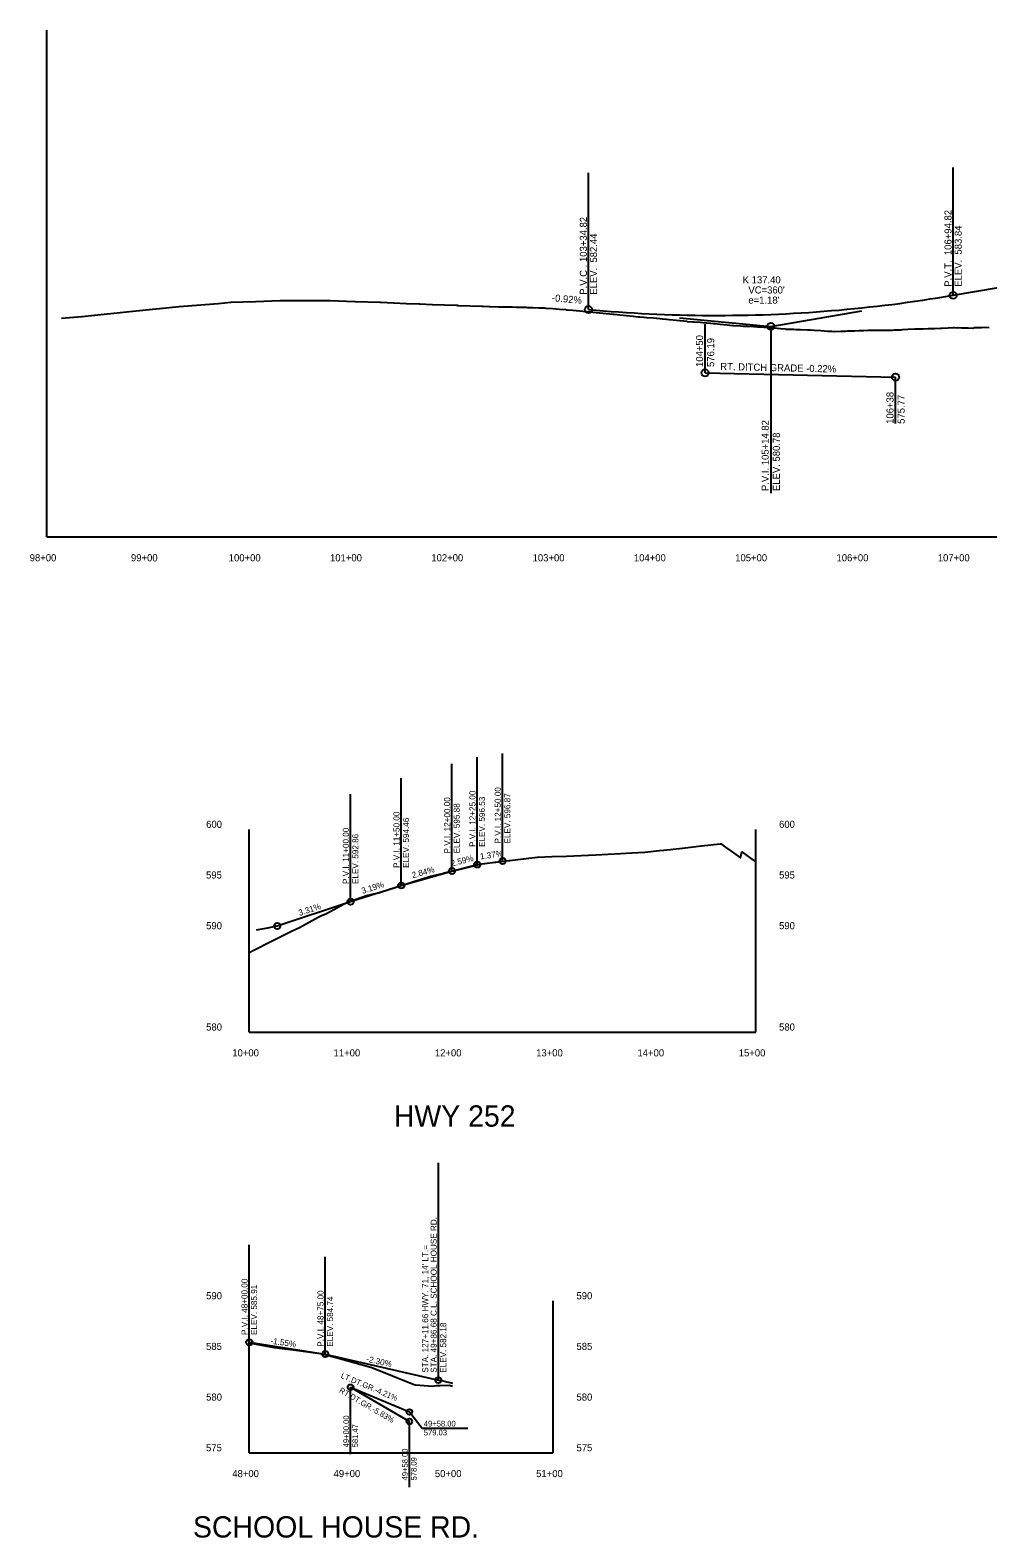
# Model space of a CAD drawing. Extents: x 634057 to 641016, y 287858 to 292331.
# Drawn here: x 637399 to 638345, y 287858 to 289346 of the extents above; entities that cross this region are included whole.
import ezdxf

# ---------------------------------------------------------------- set-up
doc = ezdxf.new("R2010")
doc.units = 0
for name, color, linetype in [('R_Axis', 7, 'Continuous'), ('R_Axis Annot', 7, 'Continuous'), ('R_Fin Surface', 7, 'Continuous'), ('R_No Plot', 7, 'Continuous'), ('R_ROW', 7, 'Continuous'), ('R_Vert Alg', 7, 'Continuous'), ('R_Vert Alg Annot', 7, 'Continuous')]:
    doc.layers.add(name, color=color, linetype=linetype)

msp = doc.modelspace()

# ---------------------------------------------------------------- linework, layer by layer
at = {"layer": 'R_Axis'}
for p, q in [((637415.8, 288845.5), (637415.8, 289345.5)), ((637415.8, 288845.5), (640715.8, 288845.5)), ((637615.8, 288357), (637615.8, 288557)), ((638115.8, 288357), (638115.8, 288557)), ((637615.8, 288357), (638115.8, 288357)), ((637615.8, 287941.9), (637615.8, 288091.9)), ((637915.8, 287941.9), (637915.8, 288091.9)), ((637615.8, 287941.9), (637915.8, 287941.9))]:
    msp.add_line(p, q, dxfattribs=at)
at = {"layer": 'R_Fin Surface'}
for points in [[(637623, 288457.9), (637634.2, 288460), (637643.4, 288461.7)], [(637802.5, 288013.6), (637806.7, 288012.8), (637816.5, 288010.7)]]:
    msp.add_lwpolyline(points, dxfattribs=at)
at = {"layer": 'R_No Plot'}
for points in [[(637430.3, 289061.4), (637450.5, 289063.1), (637450.8, 289063.1), (637463.1, 289064.4), (637463.3, 289064.4), (637475.6, 289065.7), (637475.9, 289065.7), (637488.2, 289067.1), (637488.4, 289067.1), (637500.7, 289068.4), (637523.6, 289070.6), (637523.7, 289070.6), (637527, 289070.9), (637546.6, 289072.8), (637546.7, 289072.8), (637559.3, 289073.8), (637559.4, 289073.9), (637572.1, 289074.9), (637572.2, 289074.9), (637584.9, 289075.9), (637585, 289075.9), (637597.6, 289077), (637597.8, 289077), (637621.9, 289077.9), (637622.2, 289077.9), (637646.1, 289078.8), (637646.6, 289078.8), (637670.7, 289078.8), (637671.3, 289078.8), (637695.4, 289078.8), (637695.7, 289078.7), (637719.9, 289077.9), (637720.3, 289077.9), (637720.7, 289077.9), (637744.8, 289077.1), (637745.3, 289077), (637745.8, 289077), (637758, 289076.5), (637758.6, 289076.5), (637770.7, 289076), (637771.3, 289076), (637783.4, 289075.5), (637784.1, 289075.5), (637796.2, 289075), (637796.8, 289075), (637820.4, 289074.1), (637821.2, 289074.1), (637821.9, 289074), (637845.3, 289073.2), (637846.2, 289073.1), (637846.4, 289073.1), (637852.5, 289072.8), (637853.3, 289072.8), (637853.4, 289072.8), (637862.3, 289072.6), (637866.5, 289072.6), (637866.7, 289072.6), (637869, 289072.5), (637875.6, 289072.4), (637879.7, 289072.3), (637879.9, 289072.3), (637882.2, 289072.2), (637888.8, 289072.1), (637890.6, 289072), (637893, 289071.9), (637895.4, 289071.8), (637902, 289071.6), (637905.8, 289071.4), (637906.3, 289071.4), (637906.8, 289071.4), (637908.7, 289071.2), (637915.3, 289070.8), (637921.9, 289070.3), (637928.2, 289069.8), (637928.5, 289069.7), (637929.5, 289069.6), (637935.1, 289069.2), (637941.8, 289068.6), (637948.4, 289068), (637948.5, 289067.9), (637950.8, 289067.7), (637953.4, 289067.5), (637955, 289067.3), (637961.6, 289066.7), (637968.2, 289066.1), (637971.7, 289065.8), (637974.8, 289065.4), (637975.2, 289065.4), (637979.1, 289065), (637981.5, 289064.8), (637988.1, 289064), (637994.7, 289063.3), (637994.7, 289063.3), (637999.7, 289062.7), (638001.3, 289062.6), (638005.3, 289062.2), (638007.9, 289062), (638014.6, 289061.6), (638017.7, 289061.3), (638021.2, 289061), (638023.6, 289060.8), (638027.8, 289060.3), (638030.2, 289060.1), (638034.4, 289059.7), (638040.9, 289059.1), (638041, 289059.1), (638047.6, 289058.3), (638048.1, 289058.2), (638053.3, 289057.9), (638054.3, 289057.8), (638060.9, 289057.3), (638066.5, 289056.8), (638067.5, 289056.7), (638071.1, 289056.4), (638074.1, 289056.1), (638075.1, 289056), (638080.7, 289055.5), (638087.4, 289054.8), (638090.1, 289054.5), (638093.1, 289054.2), (638094, 289054.1), (638100.6, 289053.8), (638103.7, 289053.6), (638106.6, 289053.5), (638107.2, 289053.5), (638113.8, 289053.1), (638117.6, 289052.8), (638120, 289052.7), (638120.4, 289052.7), (638127.1, 289052.2), (638131.5, 289051.8), (638132.9, 289051.7), (638133.7, 289051.7), (638140.3, 289051.1), (638145.1, 289050.7), (638145.4, 289050.6), (638146.9, 289050.6), (638153.5, 289050.4), (638155.2, 289050.3), (638160.1, 289050.2), (638166.8, 289049.9), (638168.5, 289049.8), (638169.2, 289049.7), (638169.9, 289049.7), (638173.4, 289049.5), (638180, 289049.1), (638186.6, 289048.7), (638191, 289048.4), (638193.2, 289048.2), (638193.4, 289048.2), (638199.9, 289048.5), (638204.3, 289048.7), (638206.5, 289048.8), (638207.8, 289048.8), (638213.1, 289049), (638217.8, 289049.1), (638219.7, 289049.2), (638222.2, 289049.3), (638226.3, 289049.4), (638231, 289049.4), (638232.9, 289049.5), (638236.6, 289049.5), (638239.6, 289049.5), (638244, 289049.6), (638246.2, 289049.6), (638251.1, 289049.6), (638252.8, 289049.7), (638259.4, 289050), (638260.7, 289050.1), (638266, 289050.4), (638272.7, 289050.7), (638274.8, 289050.7), (638279.3, 289050.9), (638281, 289051), (638285.9, 289051.1), (638292.5, 289051.3), (638298.3, 289051.4), (638299.1, 289051.5), (638299.9, 289051.5), (638305.7, 289051.8), (638311.1, 289052), (638312.4, 289052), (638314.8, 289051.9), (638315.1, 289052), (638319, 289051.9), (638325.6, 289051.7), (638330.1, 289051.6), (638331.6, 289052), (638332.2, 289052), (638338.8, 289052.3), (638338.8, 289052.3), (638341.8, 289052.4), (638346.3, 289052)], [(637615.8, 288434.9), (637619.5, 288437.6), (637636.9, 288446.3), (637640.4, 288448), (637658.8, 288457.2), (637661.8, 288458.7), (637665.2, 288460.3), (637683.7, 288470.3), (637686.4, 288471.6), (637692, 288473.9), (637710.2, 288484), (637714.8, 288485.8), (637731.4, 288491.6), (637737.2, 288493), (637745.1, 288494.8), (637745.3, 288494.9), (637759.7, 288499.7), (637769.5, 288502.8), (637769.8, 288502.9), (637770.1, 288503), (637793.8, 288510.5), (637794.8, 288510.8), (637806.6, 288513.6), (637808.3, 288514), (637820.1, 288516.9), (637832.1, 288519.8), (637833.5, 288520.1), (637845.4, 288523), (637858.6, 288524.6), (637859.2, 288524.7), (637872.4, 288526.2), (637872.9, 288526.3), (637886.2, 288527.9), (637886.6, 288527.9), (637900, 288529.5), (637900.4, 288529.6), (637914.4, 288530.1), (637914.7, 288530.1), (637928.9, 288530.7), (637929.1, 288530.7), (637943.3, 288531.2), (637943.5, 288531.2), (637957.8, 288531.8), (637957.9, 288531.8), (637982.1, 288533.2), (637982.2, 288533.2), (637993.5, 288533.8), (638006.3, 288534.5), (638006.4, 288534.5), (638020.6, 288536.1), (638025, 288536.6), (638025, 288536.6), (638043.5, 288538.6), (638043.6, 288538.6), (638062, 288540.6), (638062.2, 288540.6), (638080.5, 288542.6), (638080.8, 288542.6), (638081.2, 288542.6), (638100.6, 288529), (638102, 288534.8), (638115.5, 288524.9)]]:
    msp.add_lwpolyline(points, dxfattribs=at)
at = {"layer": 'R_ROW'}
msp.add_lwpolyline([(637615.8, 288050.1), (637616.1, 288050.1), (637619, 288049.6), (637640.4, 288045.8), (637643.1, 288045.5), (637664.3, 288042.7), (637666.7, 288042.4), (637688.2, 288039.6), (637690.3, 288039), (637712, 288032.9), (637734.3, 288026.7), (637735.7, 288026.3), (637756.5, 288018.1), (637757.7, 288017.6), (637778.7, 288009.3), (637779.7, 288008.9), (637780, 288008.9), (637796.9, 288007.8), (637800.6, 288008.4), (637804.3, 288008.4), (637813.3, 288008.7), (637816.5, 288007.7)], dxfattribs=at)
at = {"layer": 'R_Vert Alg'}
for p, q in [((637950.6, 289069.9), (637950.6, 289204.6)), ((638310.6, 289083.9), (638310.6, 289209.9)), ((638310.6, 289083.9), (638560.8, 289126.4)), ((638040.6, 289061.6), (638130.6, 289053.3)), ((638130.6, 289053.3), (638220.6, 289068.6)), ((638065.8, 289007.4), (638065.8, 289055.6)), ((638130.6, 289053.3), (638130.6, 288888.7)), ((638065.8, 289007.4), (638253.8, 289003.2)), ((638253.8, 288957.6), (638253.8, 289003.2)), ((637840.8, 288522.3), (637840.8, 288628.3)), ((637865.8, 288525.7), (637865.8, 288631.7)), ((637815.8, 288515.8), (637815.8, 288621.8)), ((637765.8, 288501.6), (637765.8, 288607.6)), ((637715.8, 288485.7), (637715.8, 288591.7)), ((637815.8, 288515.8), (637840.8, 288522.3)), ((637840.8, 288522.3), (637865.8, 288525.7)), ((637765.8, 288501.6), (637815.8, 288515.8)), ((637715.8, 288485.7), (637765.8, 288501.6)), ((637643.4, 288461.7), (637715.8, 288485.7)), ((637802.5, 288013.6), (637802.5, 288228.1)), ((637615.8, 288051), (637615.8, 288147)), ((637690.8, 288039.3), (637690.8, 288135.3)), ((637615.8, 288051), (637690.8, 288039.3)), ((637690.8, 288039.3), (637802.5, 288013.6)), ((637715.8, 287940.5), (637715.8, 288006.6)), ((637715.8, 288006.6), (637773.8, 287972.8)), ((637715.8, 288006.6), (637773.8, 287982.2)), ((637773.8, 287982.2), (637786.5, 287966.3)), ((637773.8, 287907.9), (637773.8, 287972.8)), ((637786.5, 287966.3), (637831.7, 287966.3))]:
    msp.add_line(p, q, dxfattribs=at)
msp.add_lwpolyline([(637950.6, 289069.9), (637958.1, 289069.2), (637965.6, 289068.6), (637973.1, 289068), (637980.6, 289067.5), (637988.1, 289067), (637995.6, 289066.5), (638003.1, 289066.1), (638010.6, 289065.7), (638018.1, 289065.3), (638025.6, 289065), (638033.1, 289064.8), (638040.6, 289064.6), (638048.1, 289064.4), (638055.6, 289064.2), (638063.1, 289064.1), (638070.6, 289064.1), (638078.1, 289064.1), (638085.6, 289064.1), (638093.1, 289064.2), (638100.6, 289064.3), (638108.1, 289064.4), (638115.6, 289064.6), (638123.1, 289064.8), (638138.1, 289065.4), (638145.6, 289065.8), (638153.1, 289066.2), (638160.6, 289066.6), (638168.1, 289067.1), (638175.6, 289067.6), (638183.1, 289068.2), (638190.6, 289068.8), (638198.1, 289069.4), (638205.6, 289070.1), (638213.1, 289070.8), (638220.6, 289071.6), (638228.1, 289072.4), (638235.6, 289073.2), (638243.1, 289074.1), (638250.6, 289075), (638258.1, 289076), (638265.6, 289077), (638273.1, 289078.1), (638280.6, 289079.1), (638288.1, 289080.3), (638295.6, 289081.4), (638303.1, 289082.7), (638310.6, 289083.9)], dxfattribs=at)
for centre, radius in [((638310.6, 289083.9), 3.5), ((637950.6, 289069.9), 3.5), ((638130.6, 289053.3), 3.5), ((638065.8, 289007.4), 3.5), ((638253.8, 289003.2), 3.5), ((637840.8, 288522.3), 3), ((637865.8, 288525.7), 3), ((637815.8, 288515.8), 3), ((637765.8, 288501.6), 3), ((637715.8, 288485.7), 3), ((637643.4, 288461.7), 3), ((637615.8, 288051), 3), ((637690.8, 288039.3), 3), ((637802.5, 288013.6), 3), ((637715.8, 288006.6), 2.8), ((637715.8, 288006.6), 2.8), ((637773.8, 287982.2), 2.8), ((637773.8, 287972.8), 2.8)]:
    msp.add_circle(centre, radius, dxfattribs=at)

# ---------------------------------------------------------------- texts
at = {"layer": 'R_Axis Annot'}
for s, height, p in [('98+00', 7, (637399, 288821.5)), ('99+00', 7, (637499, 288821.5)), ('100+00', 7, (637595.5, 288821.5)), ('101+00', 7, (637695.5, 288821.5)), ('102+00', 7, (637795.5, 288821.5)), ('103+00', 7, (637895.5, 288821.5)), ('104+00', 7, (637995.5, 288821.5)), ('105+00', 7, (638095.5, 288821.5)), ('106+00', 7, (638195.5, 288821.5)), ('107+00', 7, (638295.5, 288821.5)), ('600', 7, (637573.2, 288558.5)), ('600', 7, (637573.2, 288558.5)), ('600', 7, (638138.8, 288558.5)), ('600', 7, (638138.8, 288558.5)), ('595', 7, (637573.1, 288508.5)), ('595', 7, (638138.8, 288508.5)), ('590', 7, (637573.2, 288458.5)), ('590', 7, (638138.8, 288458.5)), ('580', 7, (637573.2, 288358.5)), ('580', 7, (638138.8, 288358.5)), ('10+00', 7, (637599, 288333)), ('11+00', 7, (637699, 288333)), ('12+00', 7, (637799, 288333)), ('13+00', 7, (637899, 288333)), ('14+00', 7, (637999, 288333)), ('15+00', 7, (638099, 288333)), ('HWY 252', 21, (637758.5, 288263.7)), ('590', 7, (637573.2, 288093.4)), ('590', 7, (637573.2, 288093.4)), ('590', 7, (637938.8, 288093.4)), ('590', 7, (637938.8, 288093.4)), ('585', 7, (637573.1, 288043.4)), ('585', 7, (637938.8, 288043.4)), ('580', 7, (637573.2, 287993.4)), ('580', 7, (637938.8, 287993.4)), ('575', 7, (637573.1, 287943.4)), ('575', 7, (637938.8, 287943.4)), ('48+00', 7, (637599, 287917.9)), ('49+00', 7, (637699, 287917.9)), ('50+00', 7, (637799, 287917.9)), ('51+00', 7, (637899, 287917.9)), ('SCHOOL HOUSE RD.', 21, (637560.2, 287858.3))]:
    msp.add_text(s, height=height, dxfattribs=at).set_placement(p)
at = {"layer": 'R_Vert Alg Annot'}
for s, height, rotation, p in [('P.V.C . 103+34.82', 7, 90, (637949.1, 289084.5)), ('P.V.T.  106+94.82', 7, 90, (638309.1, 289092.4)), ('ELEV.  583.84', 7, 90, (638319.1, 289092.4)), ('ELEV.  582.44', 7, 90, (637959.1, 289084.5)), ('-0.92%', 7, 354.7334, (637914.3, 289078.1)), ('104+50', 7, 90, (638063.8, 289013.2)), ('576.19', 7, 90, (638074.8, 289013.2)), ('RT. DITCH GRADE -0.22%', 7, 358.7202, (638080.7, 289010.3)), ('106+38', 7, 90, (638251.8, 288957.1)), ('575.77', 7, 90, (638262.8, 288957.1)), ('P.V.I. 105+14.82', 7, 90, (638128.6, 288890.8)), ('ELEV. 580.78', 7, 90, (638139.6, 288890.8)), ('P.V.I. 12+25.00', 6, 90, (637839.1, 288539.7)), ('P.V.I. 12+50.00', 6, 90, (637864.1, 288543.1)), ('P.V.I. 12+00.00', 6, 90, (637814.1, 288533.2)), ('ELEV. 595.88', 6, 90, (637823.5, 288533.2)), ('ELEV. 596.53', 6, 90, (637848.5, 288539.7)), ('ELEV. 596.87', 6, 90, (637873.5, 288543.1)), ('P.V.I. 11+50.00', 6, 90, (637764.1, 288519)), ('ELEV. 594.46', 6, 90, (637773.5, 288519)), ('P.V.I. 11+00.00', 6, 90, (637714.1, 288503.1)), ('ELEV. 592.86', 6, 90, (637723.5, 288503.1)), ('1.37%', 6, 7.7893, (637844, 288527.3)), ('2.84%', 6, 15.8732, (637777.2, 288508.7)), ('2.59%', 6, 14.5193, (637815.6, 288520.3)), ('3.19%', 6, 17.67, (637727.7, 288493.3)), ('3.31%', 6, 18.3377, (637665.5, 288471.5)), ('STA. 49+86.68 C.L. SCHOOL HOUSE RD.', 6, 90, (637800.8, 288020.9)), ("STA. 127+11.66 HWY. 71, 14' LT.=", 6, 90, (637792.4, 288020.9)), ('P.V.I. 48+00.00', 6, 90, (637614.1, 288058.2)), ('ELEV. 585.91', 6, 90, (637623.5, 288058.2)), ('P.V.I. 48+75.00', 6, 90, (637689.1, 288046.6)), ('ELEV. 584.74', 6, 90, (637698.5, 288046.6)), ('ELEV. 582.18', 6, 90, (637810.2, 288020.9)), ('-1.55%', 6, 351.165, (637636.4, 288049.7)), ('-2.30%', 6, 347.0529, (637730.9, 288031.9)), ('LT.DT.GR.-4.21%', 5.6, 337.184, (637705.6, 288016)), ('RT.DT.GR.-5.83%', 5.6, 329.7681, (637704, 288001.9)), ('49+00.00', 5.6, 90, (637714.2, 287947.3)), ('581.47', 5.6, 90, (637723, 287947.3)), ('49+58.00', 5.6, 90, (637772.2, 287914.7)), ('578.09', 5.6, 90, (637781, 287914.7))]:
    msp.add_text(s, height=height, rotation=rotation, dxfattribs=at).set_placement(p)
for s, height, p in [('K 137.40', 7, (638102.9, 289095.7)), ("VC=360'", 7, (638108.5, 289085.7)), ("e=1.18'", 7, (638108.5, 289075.7)), ('49+58.00', 5.6, (637788.1, 287967.9)), ('579.03', 5.6, (637788.1, 287959.1))]:
    msp.add_text(s, height=height, dxfattribs=at).set_placement(p)

doc.saveas('drawing.dxf')
